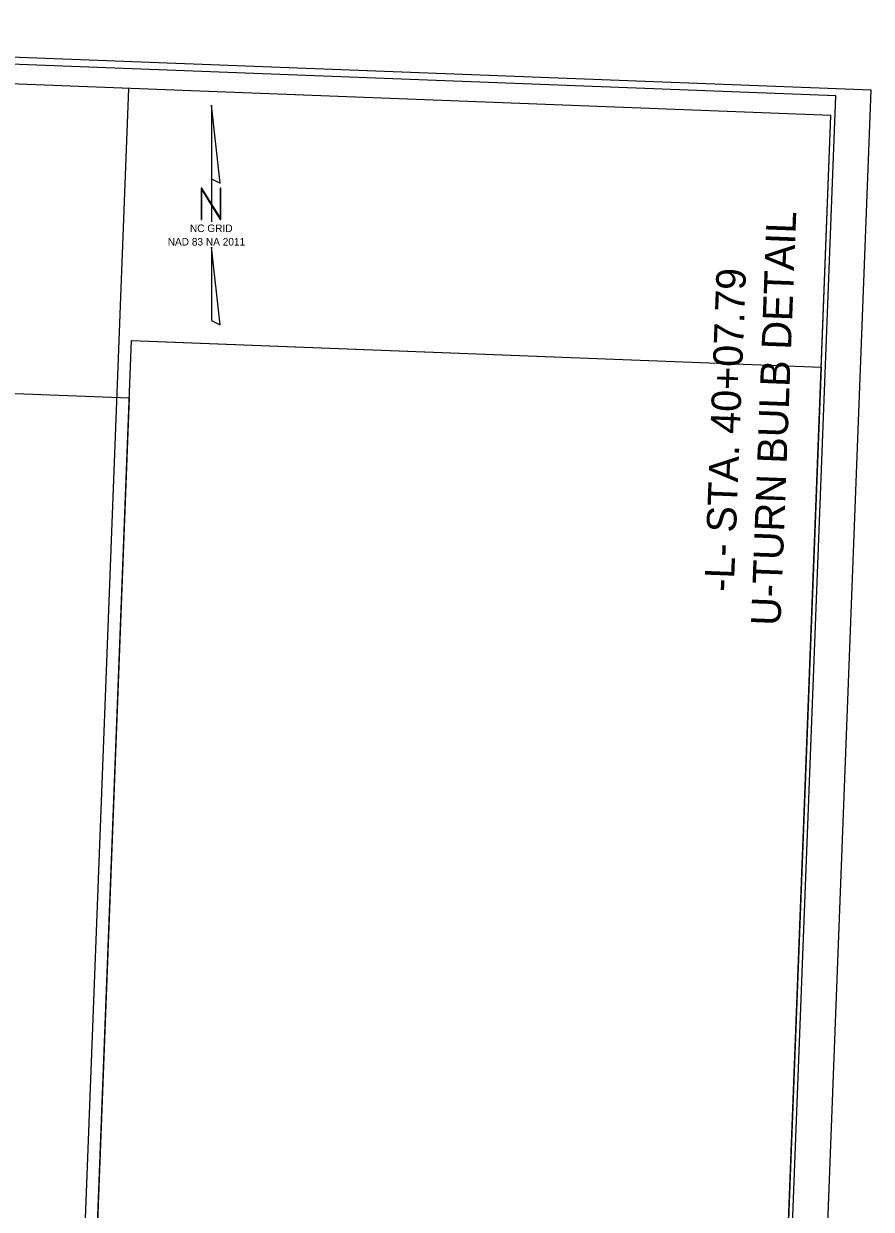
# Model space of a CAD drawing. Extents: x 2097521 to 2097987, y 686521 to 687299.
# Drawn here: x 2097771.5 to 2097987, y 686910 to 687211.1 of the extents above; entities that cross this region are included whole.
import ezdxf

# ---------------------------------------------------------------- set-up
doc = ezdxf.new("R2010")
doc.units = 0
for name, color, linetype in [('Default', 7, 'Continuous'), ('Matchline', 7, 'Continuous'), ('Prop Dimension', 7, 'Continuous'), ('Sheet Layout Plan Border', 7, 'Continuous'), ('Sheet Plot Border Inside CELL', 7, 'Continuous'), ('Sheet Plot Border Outside CELL', 7, 'Continuous'), ('Sheet Profile CELL', 7, 'Continuous')]:
    doc.layers.add(name, color=color, linetype=linetype)

msp = doc.modelspace()

# ---------------------------------------------------------------- linework, layer by layer
at = {"layer": 'Default'}
msp.add_line((2097819.27, 687162.47), (2097819.27, 687162.47), dxfattribs=at)
for points in [[(2097819.22, 687190.4), (2097819.22, 687171.73), (2097821.42, 687170.63)], [(2097816.59, 687161.42), (2097816.81, 687161.42), (2097816.81, 687168.89), (2097821.42, 687161.42), (2097821.64, 687161.42), (2097821.64, 687169.32), (2097821.42, 687169.32), (2097821.42, 687161.86), (2097816.81, 687169.32), (2097816.59, 687169.32)], [(2097819.22, 687135.73), (2097821.42, 687134.64), (2097819.22, 687154.39)]]:
    msp.add_lwpolyline(points, close=True, dxfattribs=at)
msp.add_lwpolyline([(2097819.22, 687171.73), (2097819.22, 687160.76)], dxfattribs=at)
at = {"layer": 'Matchline'}
msp.add_line((2097803.36, 687130.45), (2097906.36, 687126.5), dxfattribs=at)
at = {"layer": 'Sheet Layout Plan Border'}
for points in [[(2097779.69, 686630.99), (2097798.86, 687130.62), (2097974.25, 687123.89), (2097955.08, 686624.26)], [(2097534.78, 686624.29), (2097553.94, 687123.99), (2097611.01, 687121.8), (2097611.07, 687123.23), (2097798.3, 687116.05), (2097794.51, 687017.17), (2097779.16, 686617.13)]]:
    msp.add_lwpolyline(points, close=True, dxfattribs=at)
at = {"layer": 'Sheet Plot Border Inside CELL'}
msp.add_lwpolyline([(2097952.36, 686526.7), (2097977.91, 687192.81), (2097556.18, 687208.99), (2097530.63, 686542.88)], close=True, dxfattribs=at)
at = {"layer": 'Sheet Plot Border Outside CELL'}
msp.add_lwpolyline([(2097961.14, 686521.16), (2097986.95, 687194.27), (2097547.28, 687211.13), (2097521.46, 686538.02)], close=True, dxfattribs=at)
at = {"layer": 'Sheet Profile CELL'}
for p, q in [((2097798.1, 687194.7), (2097775.11, 686595.14)), ((2097953.71, 686588.3), (2097976.7, 687187.85))]:
    msp.add_line(p, q, dxfattribs=at)
msp.add_lwpolyline([(2097557.01, 687203.95), (2097534.01, 686604.39), (2097953.71, 686588.3), (2097976.7, 687187.85)], close=True, dxfattribs=at)

# ---------------------------------------------------------------- texts
at = {"layer": 'Default'}
for s, p in [('NC GRID', (2097813.76, 687158.2)), ('NAD 83 NA 2011', (2097808.1, 687154.78))]:
    msp.add_text(s, height=1.92, rotation=360, dxfattribs=at).set_placement(p)
at = {"layer": 'Prop Dimension'}
for s, p in [('U-TURN BULB DETAIL', (2097963.85, 687058.09)), ('-L- STA. 40+07.79', (2097951.98, 687066.74))]:
    msp.add_text(s, height=7.5, rotation=87.8037, dxfattribs=at).set_placement(p)

doc.saveas('drawing.dxf')
